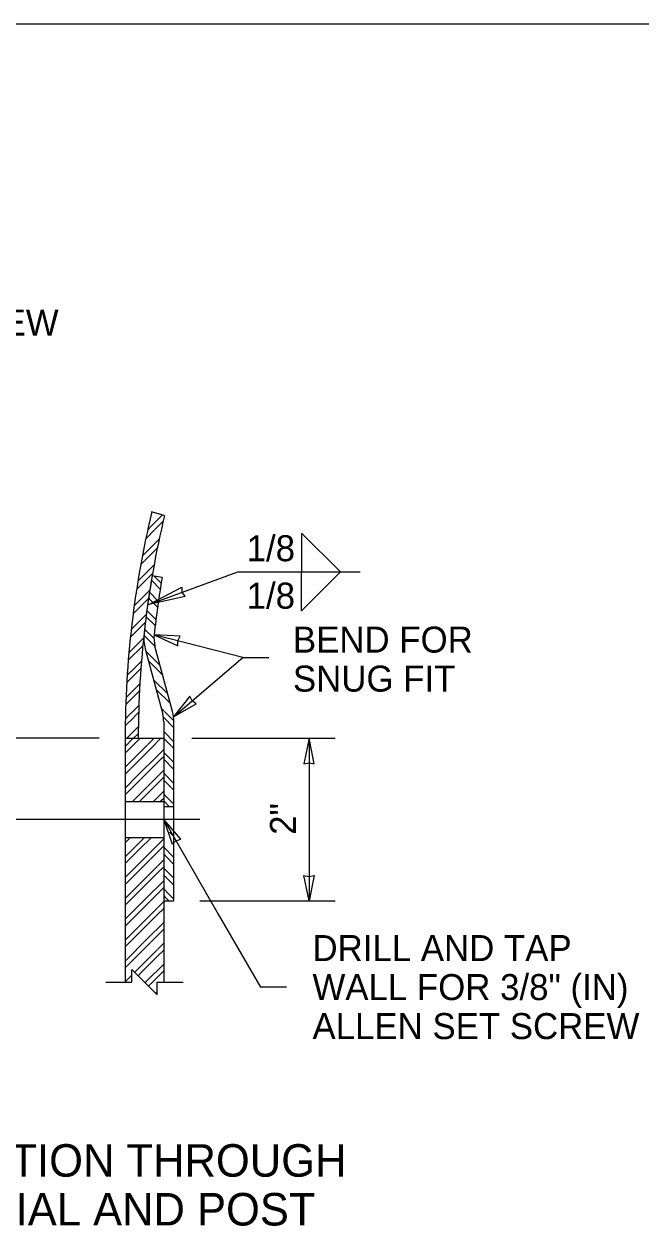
# Model space of a CAD drawing. Extents: x 99862 to 104211, y 98939 to 111076.
# Drawn here: x 100755 to 101134, y 104336 to 105075 of the extents above; entities that cross this region are included whole.
import ezdxf

# ---------------------------------------------------------------- set-up
doc = ezdxf.new("R2010")
doc.units = 0
for name, color, linetype in [('Level 10', 7, 'Continuous'), ('Level 15', 7, 'Continuous'), ('Level 2', 7, 'Continuous'), ('Level 20', 7, 'Continuous'), ('Level 3', 7, 'Continuous'), ('Level 5', 7, 'Continuous'), ('Level 60', 7, 'Continuous')]:
    doc.layers.add(name, color=color, linetype=linetype)

msp = doc.modelspace()

# ---------------------------------------------------------------- linework, layer by layer
at = {"layer": 'Level 10'}
for p, q in [((100925.54, 104761.97), (100949.44, 104738.07)), ((100925.54, 104761.97), (100925.54, 104737.97)), ((100831.52, 104717.95), (100886.35, 104738.07)), ((100886.35, 104738.07), (100961.44, 104738.07)), ((100925.54, 104714.17), (100925.54, 104738.17)), ((100925.54, 104714.17), (100949.44, 104738.07))]:
    msp.add_line(p, q, dxfattribs=at)
msp.add_lwpolyline([(100831.52, 104717.95), (100851.93, 104728.62), (100851.96, 104725.45), (100853.98, 104723.01)], close=True, dxfattribs=at)
at = {"layer": 'Level 15'}
for p, q in [((100889.34, 104685.55), (100834.85, 104699.38)), ((100846.79, 104649.07), (100889.34, 104685.55)), ((100889.34, 104685.55), (100905.34, 104685.55)), ((100801.05, 104635.77), (100729.05, 104635.77)), ((100858.05, 104635.77), (100946.05, 104635.77)), ((100930.05, 104635.77), (100930.05, 104535.77)), ((100863, 104585.77), (100729.05, 104585.77)), ((100840.75, 104585.74), (100874.26, 104527.71)), ((100874.26, 104527.71), (100900.19, 104482.79)), ((100916.19, 104482.79), (100900.19, 104482.79))]:
    msp.add_line(p, q, dxfattribs=at)
for points in [[(100834.85, 104699.38), (100849.35, 104692.56), (100849.4, 104695.73), (100850.85, 104698.55)], [(100846.79, 104649.07), (100860.75, 104656.93), (100858.2, 104658.8), (100856.75, 104661.62)], [(100930.05, 104635.77), (100926.97, 104620.05), (100930.05, 104620.77), (100933.14, 104620.05)], [(100840.75, 104585.74), (100845.94, 104570.58), (100848.25, 104572.75), (100851.29, 104573.66)], [(100930.05, 104535.77), (100926.97, 104551.5), (100930.05, 104550.77), (100933.14, 104551.5)]]:
    msp.add_lwpolyline(points, close=True, dxfattribs=at)
msp.add_lwpolyline([(100805.16, 104485.77), (100821.16, 104485.77), (100821.16, 104493.52), (100836.65, 104478.03), (100836.65, 104485.77), (100852.65, 104485.77)], dxfattribs=at)
at = {"layer": 'Level 2'}
msp.add_line((100863, 104535.77), (100946.05, 104535.77), dxfattribs=at)
at = {"layer": 'Level 3'}
for p, q in [((100833.12, 104775.19), (100840.88, 104772.94)), ((100817.05, 104635.77), (100817.05, 104635.77)), ((100817.05, 104635.77), (100817.05, 104485.77)), ((100817.05, 104635.77), (100829.55, 104635.77)), ((100817.05, 104626.59), (100826.23, 104635.77)), ((100817.05, 104630.83), (100821.99, 104635.77)), ((100829.55, 104635.77), (100840.75, 104635.77)), ((100829.55, 104635.77), (100829.55, 104635.77)), ((100830.94, 104631.9), (100834.81, 104635.77)), ((100833.06, 104629.78), (100839.05, 104635.77)), ((100840.75, 104635.77), (100840.75, 104485.77)), ((100818.12, 104619.09), (100830.85, 104631.82)), ((100820.24, 104616.97), (100832.97, 104629.69)), ((100837.35, 104625.5), (100840.75, 104628.9)), ((100824.53, 104612.68), (100837.26, 104625.41)), ((100826.65, 104610.56), (100839.38, 104623.29)), ((100839.47, 104623.37), (100840.75, 104624.66)), ((100817.05, 104618.02), (100818.04, 104619)), ((100817.05, 104613.77), (100820.16, 104616.88)), ((100830.94, 104606.27), (100840.75, 104616.08)), ((100817.05, 104605.2), (100824.44, 104612.59)), ((100817.05, 104600.96), (100826.56, 104610.47)), ((100821.38, 104596.71), (100830.85, 104606.18)), ((100833.06, 104604.15), (100840.75, 104611.84)), ((100825.62, 104596.71), (100832.97, 104604.06)), ((100834.19, 104596.71), (100837.26, 104599.77)), ((100837.35, 104599.86), (100840.75, 104603.27)), ((100839.47, 104597.74), (100840.75, 104599.03)), ((100840.75, 104596.71), (100817.05, 104596.71)), ((100838.44, 104596.71), (100839.38, 104597.65)), ((100817.05, 104574.83), (100840.75, 104574.83)), ((100817.05, 104571.54), (100819.64, 104574.13)), ((100817.05, 104562.97), (100823.93, 104569.84)), ((100819.73, 104574.22), (100820.34, 104574.83)), ((100824.01, 104569.93), (100828.92, 104574.83)), ((100826.13, 104567.81), (100833.16, 104574.83)), ((100830.42, 104563.52), (100840.75, 104573.85)), ((100832.54, 104561.4), (100840.75, 104569.61)), ((100817.05, 104558.73), (100826.05, 104567.72)), ((100817.61, 104550.71), (100830.33, 104563.44)), ((100819.73, 104548.59), (100832.45, 104561.31)), ((100824.01, 104544.3), (100836.74, 104557.03)), ((100826.13, 104542.18), (100838.86, 104554.91)), ((100836.83, 104557.12), (100840.75, 104561.04)), ((100838.95, 104554.99), (100840.75, 104556.8)), ((100817.05, 104550.15), (100817.52, 104550.62)), ((100817.05, 104545.91), (100819.64, 104548.5)), ((100830.42, 104537.89), (100840.75, 104548.22)), ((100817.05, 104537.34), (100823.93, 104544.21)), ((100817.05, 104533.1), (100826.05, 104542.09)), ((100832.54, 104535.77), (100840.75, 104543.98)), ((100817.61, 104525.07), (100830.33, 104537.8)), ((100819.73, 104522.95), (100832.45, 104535.68)), ((100836.83, 104531.48), (100840.75, 104535.41)), ((100817.05, 104524.52), (100817.52, 104524.99)), ((100824.01, 104518.67), (100836.74, 104531.39)), ((100826.13, 104516.55), (100838.86, 104529.27)), ((100838.95, 104529.36), (100840.75, 104531.16)), ((100817.05, 104520.28), (100819.64, 104522.86)), ((100817.05, 104511.71), (100823.93, 104518.58)), ((100830.42, 104512.26), (100840.75, 104522.59)), ((100832.54, 104510.14), (100840.75, 104518.35)), ((100817.05, 104507.46), (100826.05, 104516.46)), ((100817.61, 104499.44), (100830.33, 104512.17)), ((100819.73, 104497.32), (100832.45, 104510.05)), ((100824.01, 104493.03), (100836.74, 104505.76)), ((100826.13, 104490.91), (100838.86, 104503.64)), ((100836.83, 104505.85), (100840.75, 104509.77)), ((100838.95, 104503.73), (100840.75, 104505.53)), ((100817.05, 104498.89), (100817.52, 104499.35)), ((100817.05, 104494.65), (100819.64, 104497.23)), ((100830.42, 104486.63), (100840.75, 104496.96)), ((100817.05, 104486.07), (100821.16, 104490.18)), ((100822.83, 104491.85), (100823.93, 104492.95)), ((100824.95, 104489.73), (100826.05, 104490.82)), ((100832.54, 104484.5), (100840.75, 104492.71)), ((100820.99, 104485.77), (100821.16, 104485.94)), ((100829.24, 104485.44), (100830.33, 104486.54)), ((100831.36, 104483.32), (100832.45, 104484.42)), ((100835.64, 104479.03), (100836.65, 104480.03))]:
    msp.add_line(p, q, dxfattribs=at)
at = {"layer": 'Level 5'}
for p, q in [((100833.34, 104766.43), (100840.08, 104773.17)), ((100835.46, 104764.31), (100840.51, 104769.36)), ((100829.88, 104758.73), (100835.37, 104764.22)), ((100830.95, 104764.04), (100833.25, 104766.34)), ((100827.86, 104748.14), (100838.12, 104758.4)), ((100829.05, 104745.08), (100837.08, 104753.11)), ((100824.9, 104732.36), (100833.25, 104740.71)), ((100826.86, 104742.89), (100828.96, 104744.99)), ((100833.34, 104740.8), (100834.97, 104742.43)), ((100824.22, 104727.43), (100833.92, 104737.14)), ((100833.2, 104732.94), (100838.65, 104727.49)), ((100839.81, 104734.71), (100833.65, 104735.77)), ((100834.81, 104735.57), (100839.22, 104731.16)), ((100826.93, 104721.57), (100832.27, 104726.91)), ((100832.03, 104725.54), (100834.68, 104722.89)), ((100822.15, 104712.55), (100828.96, 104719.36)), ((100822.83, 104717.47), (100826.84, 104721.48)), ((100829.05, 104719.45), (100831.6, 104722)), ((100831.44, 104721.88), (100832.56, 104720.77)), ((100832.65, 104720.68), (100837.13, 104716.2)), ((100834.77, 104722.8), (100837.63, 104719.94)), ((100820.81, 104702.63), (100830.26, 104712.09)), ((100829.99, 104710.52), (100835.6, 104704.91)), ((100830.47, 104714.28), (100836.1, 104708.65)), ((100822.64, 104700.22), (100829.6, 104707.18)), ((100829.02, 104702.92), (100834.68, 104697.26)), ((100819.57, 104688.58), (100826.84, 104695.85)), ((100820.4, 104697.98), (100822.55, 104700.14)), ((100826.93, 104695.94), (100828.36, 104697.37)), ((100828.59, 104699.1), (100832.56, 104695.13)), ((100832.65, 104695.05), (100835.44, 104692.26)), ((100834.77, 104697.17), (100834.82, 104697.11)), ((100819.16, 104683.93), (100827.96, 104692.72)), ((100829.34, 104690.87), (100840.11, 104650.66)), ((100829.74, 104689.38), (100838.58, 104680.54)), ((100846.15, 104652.27), (100835.38, 104692.48)), ((100820.52, 104676.71), (100827.25, 104683.44)), ((100831.29, 104683.59), (100838.97, 104675.91)), ((100818.11, 104670.06), (100822.55, 104674.5)), ((100818.33, 104674.53), (100820.43, 104676.63)), ((100822.64, 104674.59), (100826.89, 104678.84)), ((100839.06, 104675.82), (100840.13, 104674.75)), ((100817.77, 104661.15), (100826.18, 104669.56)), ((100834.43, 104671.88), (100834.68, 104671.62)), ((100834.77, 104671.53), (100843.27, 104663.04)), ((100835.98, 104666.08), (100844.82, 104657.24)), ((100817.61, 104656.74), (100825.87, 104665.01)), ((100817.27, 104647.83), (100820.43, 104650.99)), ((100820.52, 104651.08), (100825.65, 104656.21)), ((100822.64, 104648.96), (100825.53, 104651.85)), ((100839.12, 104654.37), (100841.09, 104652.4)), ((100841.18, 104652.31), (100846.91, 104646.58)), ((100817.11, 104643.42), (100822.55, 104648.87)), ((100818.03, 104635.77), (100825.31, 104643.05)), ((100840.34, 104648.9), (100847, 104642.24)), ((100840.75, 104645.8), (100840.75, 104535.77)), ((100847, 104535.77), (100847, 104645.8)), ((100817.05, 104635.77), (100825.12, 104635.77)), ((100822.27, 104635.77), (100825.2, 104638.7)), ((100840.75, 104639.92), (100847, 104633.67)), ((100840.75, 104635.68), (100845.38, 104631.05)), ((100845.46, 104630.96), (100847, 104629.43)), ((100840.75, 104627.1), (100841.09, 104626.77)), ((100840.75, 104622.86), (100847, 104616.61)), ((100841.18, 104626.68), (100847, 104620.85)), ((100840.75, 104614.29), (100847, 104608.04)), ((100840.75, 104610.04), (100845.38, 104605.42)), ((100840.75, 104601.47), (100841.09, 104601.13)), ((100841.18, 104601.04), (100847, 104595.22)), ((100845.46, 104605.33), (100847, 104603.79)), ((100840.75, 104597.23), (100844.39, 104593.58)), ((100847, 104593.58), (100840.75, 104593.58)), ((100847, 104593.32), (100847, 104593.58)), ((100844.36, 104577.96), (100847, 104575.31)), ((100847, 104577.96), (100847, 104578.22)), ((100840.75, 104574.83), (100840.75, 104535.77)), ((100840.75, 104568.75), (100843.85, 104565.65)), ((100840.75, 104564.5), (100841.73, 104563.53)), ((100841.81, 104563.44), (100847, 104558.25)), ((100843.94, 104565.56), (100847, 104562.5)), ((100840.75, 104555.93), (100847, 104549.68)), ((100840.75, 104551.69), (100847, 104545.44)), ((100840.75, 104543.11), (100843.85, 104540.02)), ((100843.94, 104539.93), (100847, 104536.86)), ((100840.75, 104538.87), (100841.73, 104537.9)), ((100840.75, 104535.77), (100847, 104535.77)), ((100841.81, 104537.81), (100843.85, 104535.77))]:
    msp.add_line(p, q, dxfattribs=at)
for centre, radius, start, end in [((101417.05, 104635.77), 600, 166.57341, 180), ((101418.87, 104635.46), 593.75, 166.62171, 179.96989), ((101415.75, 104635.77), 590.62, 170.25217, 173.75144), ((101415.75, 104635.77), 584.38, 170.25217, 173.75144), ((100853.49, 104697.34), 25, 173.75144, 195), ((100853.49, 104697.34), 18.75, 173.75144, 195), ((100822, 104645.8), 18.75, 0, 15), ((100822, 104645.8), 25, 0, 15)]:
    msp.add_arc(centre, radius, start, end, dxfattribs=at)
at = {"layer": 'Level 60'}
msp.add_line((103150, 105075), (100000, 105075), dxfattribs=at)

# ---------------------------------------------------------------- texts
at = {"layer": 'Level 10'}
msp.add_text('1/8', height=16, rotation=360, dxfattribs=at).set_placement((100891.73, 104744.65))
msp.add_text('1/8', height=16, dxfattribs=at).set_placement((100891.73, 104715.49))
at = {"layer": 'Level 20'}
for s, rotation, p in [('3/8" (IN) ALLEN HOLLOW SET SCREW', 360, (100391.7, 104883.44)), ('2"', 90, (100922.05, 104576.41)), ('DRILL AND TAP', 360, (100932.19, 104498.79)), ('WALL FOR 3/8" (IN)', 360, (100932.19, 104474.79)), ('ALLEN SET SCREW', 360, (100932.19, 104450.79))]:
    msp.add_text(s, height=16, rotation=rotation, dxfattribs=at).set_placement(p)
for s, height, p in [('BEND FOR', 16, (100920.17, 104688.47)), ('SNUG FIT', 16, (100920.17, 104664.47)), ('SECTION THROUGH', 20, (100691.57, 104366.18)), ('FINIAL AND POST', 20, (100706.66, 104336.18))]:
    msp.add_text(s, height=height, dxfattribs=at).set_placement(p)

doc.saveas('drawing.dxf')
